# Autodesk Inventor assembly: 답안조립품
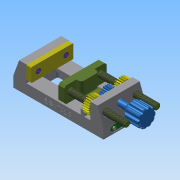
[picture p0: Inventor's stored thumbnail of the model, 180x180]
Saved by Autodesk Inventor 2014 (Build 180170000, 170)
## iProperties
Created: 2017-04
Part Number: 답안조립품
Document SubType Name: Assembly
Designer: NET
Mass: 1269.81 g
Surface Area: 784.419 cm^2
Volume: 280.83 cm^3
Density: 4.52164 g/cm^3
Author: NET
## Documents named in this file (10)
- C:\Users\NET\Desktop\370407v1019\답안조립품.iam
- C:\Users\NET\Desktop\370407v1019\바이스본체 A.ipt
- C:\Users\NET\Desktop\370407v1019\바이스본체 B.ipt
- C:\Users\NET\Desktop\370407v1019\지지대.ipt
- C:\Users\NET\Desktop\370407v1019\십자오목머리나사 M4.ipt
- C:\Users\NET\Desktop\370407v1019\고정 플레이트.ipt
- C:\Users\NET\Desktop\370407v1019\십자오목머리나사 M3.ipt
- C:\Users\NET\Desktop\370407v1019\핸들.ipt
- C:\Users\NET\Desktop\370407v1019\슬라이딩 부품.ipt
- C:\Users\NET\Desktop\370407v1019\스퍼기어.ipt
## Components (3 placed, 2 different names)
1. 고정 플레이트:1
2. 고정 플레이트:2
3. 핸들:1 — 각도:1
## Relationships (1: Angle 1)
- 각도:1 [Angle]: 핸들:1
